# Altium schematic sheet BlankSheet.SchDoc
size 431 x 279 mm; Date: Not shown in title block; ApprovedBy: Not shown in title block; CheckedBy: Not shown in title block; Author: Not shown in title block; CompanyName: Not shown in title block; Engineer: Not shown in title block; Organization: Not shown in title block; Address1: Not shown in title block; Address2: Not shown in title block; Address3: Not shown in title block; Address4: Not shown in title block; DocumentNumber: 1; Revision: Use project parameter SCH_Rev; SheetNumber: 2; SheetTotal: 3; PageSetup: Record=PageOptions¦CenterHorizontal=True¦CenterVertical=True¦PrintScale=1.00¦XCorrection=1.00¦YCorrection=1.00¦PrintKind=0¦BorderSize=5000000¦LeftOffset=0¦BottomOffset=0¦Orientation=2¦PaperLength=1000¦PaperWidth=1000¦Scale=100¦PaperSource=15¦PrintQuality=600¦MediaType=1¦DitherType=10¦PaperKind=Letter¦PrintScaleMode=1
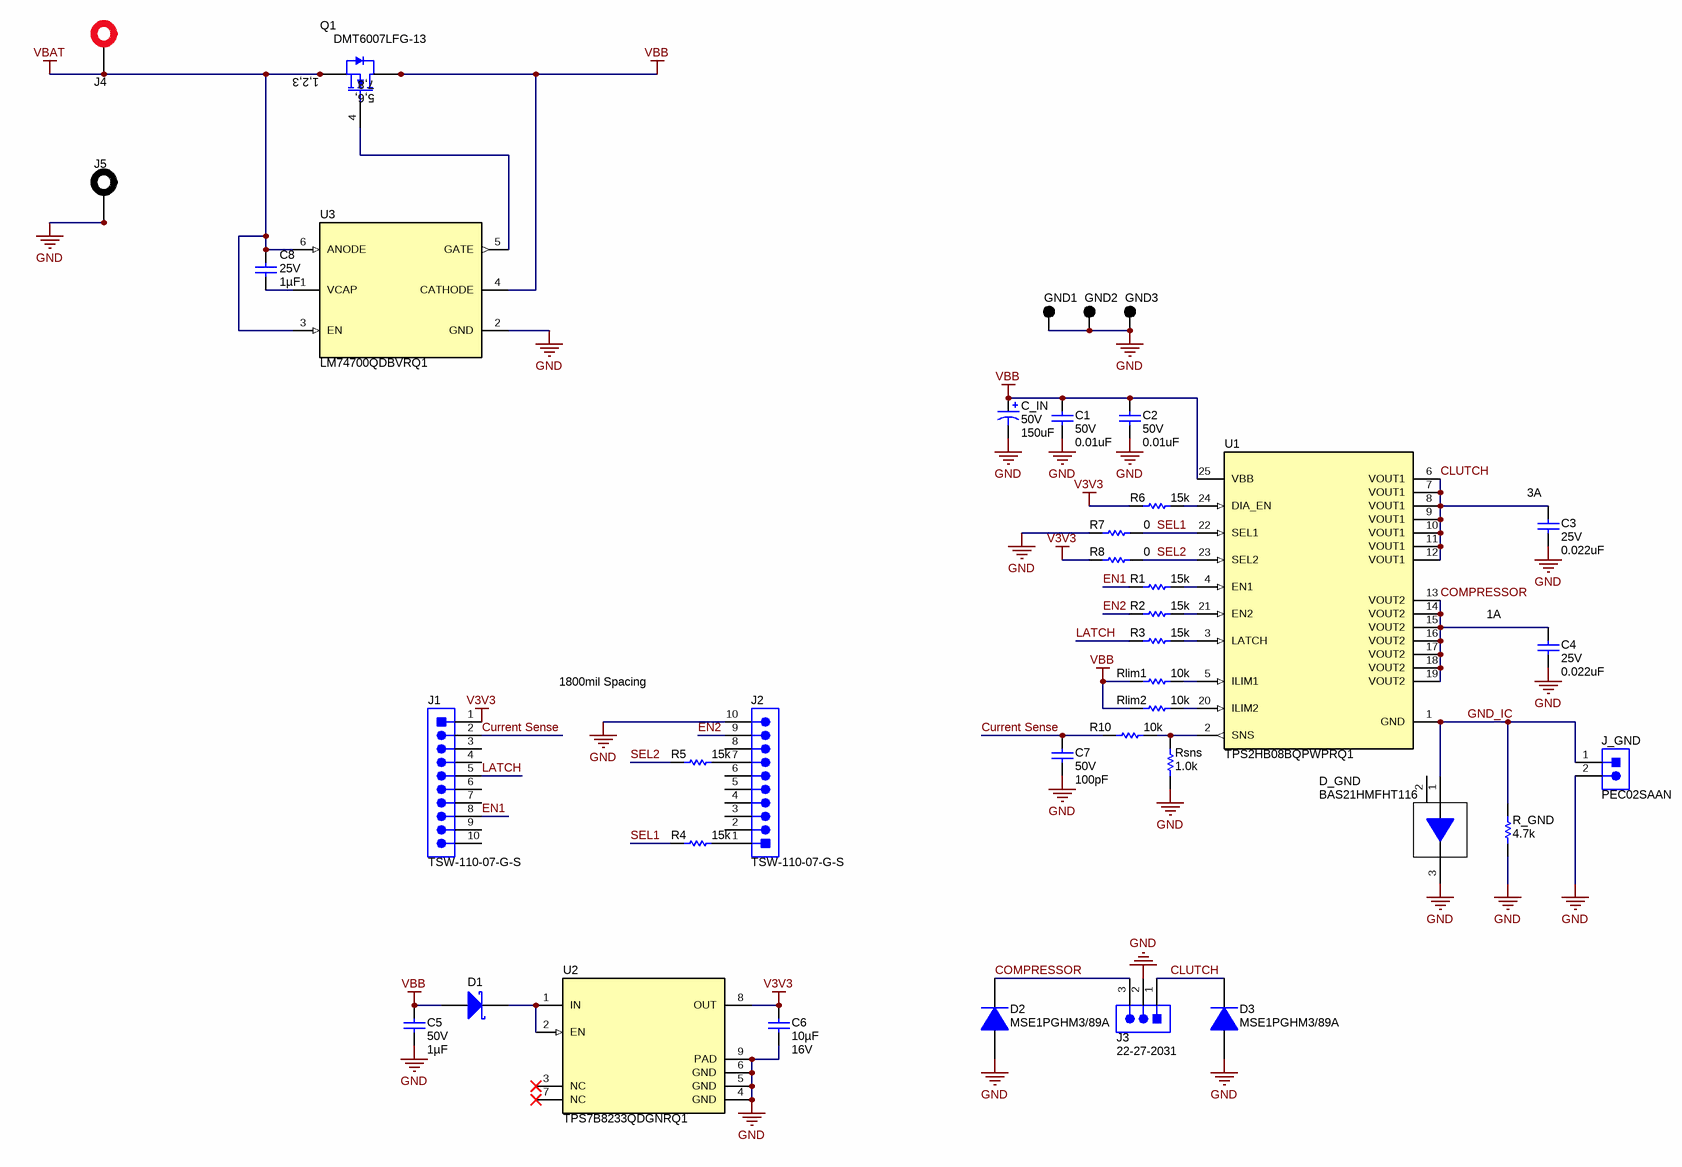
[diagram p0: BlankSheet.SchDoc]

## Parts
C1  VDC_V: 50V  ValueDisplayed: 0.01uF  [0603]  (hidden comment: GCM188R71H103KA37D)
C2  VDC_V: 50V  ValueDisplayed: 0.01uF  [0603]  (hidden comment: GCM188R71H103KA37D)
C3  VDC_V: 25V  ValueDisplayed: 0.022uF  [0603]  (hidden comment: C0603C223K3RACTU)
C4  VDC_V: 25V  ValueDisplayed: 0.022uF  [0603]  (hidden comment: C0603C223K3RACTU)
C5  VDC_V: 50V  ValueDisplayed: 1µF  [0805_HV]  (hidden comment: 08055C105K4Z2A)
C6  ValueDisplayed: 10µF  VDC_V: 16V  [0603]  (hidden comment: GRT188C81C106ME13D)
C7  VDC_V: 50V  ValueDisplayed: 100pF  [0402]  (hidden comment: CGA2B2C0G1H101J050BA)
C8  VDC_V: 25V  ValueDisplayed: 1µF  [0603]  (hidden comment: CGA3E1X7R1E105K080AD)
C_IN  VDC_V: 50V  ValueDisplayed: 150uF  [SM_RADIAL_G]  (hidden comment: EEE-FK1H151P)
D1  ZLLS400QTA  [SOD-323]  (value not drawn)
D2  MSE1PGHM3/89A  [MicroSMP]
D3  MSE1PGHM3/89A  [MicroSMP]
D_GND  BAS21HMFHT116  [SOT-23]
GND1  5011  [Keystone5011]  (value not drawn)
GND2  5011  [Keystone5011]  (value not drawn)
GND3  5011  [Keystone5011]  (value not drawn)
J1  TSW-110-07-G-S  [TSW-110-07-G-S]
J2  TSW-110-07-G-S  [TSW-110-07-G-S]
J3  22-27-2031  [MOLEX_22-27-2031]
J4  571-0500  [571-0500]  (value not drawn)
J5  571-0100  [571-0100]  (value not drawn)
J_GND  PEC02SAAN  [CONN_PEC02SAAN]
Q1  DMT6007LFG-13  [PowerDI3333-8]
R1  ValueDisplayed: 15k  [0402]  (hidden comment: CRCW040215K0JNED)
R2  ValueDisplayed: 15k  [0402]  (hidden comment: CRCW040215K0JNED)
R3  ValueDisplayed: 15k  [0402]  (hidden comment: CRCW040215K0JNED)
R4  ValueDisplayed: 15k  [0402]  (hidden comment: CRCW040215K0JNED)
R5  ValueDisplayed: 15k  [0402]  (hidden comment: CRCW040215K0JNED)
R6  ValueDisplayed: 15k  [0402]  (hidden comment: CRCW040215K0JNED)
R7  ValueDisplayed: 0  [0402]  (hidden comment: ERJ-2GE0R00X)
R8  ValueDisplayed: 0  [0402]  (hidden comment: ERJ-2GE0R00X)
R10  ValueDisplayed: 10k  [0402]  (hidden comment: CRCW040210K0JNED)
R_GND  ValueDisplayed: 4.7k  [0603]  (hidden comment: RC0603JR-074K7L)
Rlim1  ValueDisplayed: 10k  [0402]  (hidden comment: CRCW040210K0JNED)
Rlim2  ValueDisplayed: 10k  [0402]  (hidden comment: CRCW040210K0JNED)
Rsns  ValueDisplayed: 1.0k  [0603]  (hidden comment: CRCW06031K00JNEA)
U1  TPS2HB08BQPWPRQ1  [PWP0024L_N]
U2  TPS7B8233QDGNRQ1  [DGN0008D_N]
U3  LM74700QDBVRQ1  [DBV0006A_N]

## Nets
GND: C1.2 C2.2 C3.2 C4.2 C5.2 C6.2 C7.2 C_IN.2(-) D2.2(A) D3.2(A) D_GND.3(C) GND1.1 GND2.1 GND3.1 J2.10 J3.2 J5.1 J5.2 J_GND.2 R7.1 R_GND.1 Rsns.1 U2.4(GND) U2.5(GND) U2.6(GND) U2.9(PAD) U3.2(GND)
V3V3: C6.1 J1.1 R6.1 R8.1 U2.8(OUT)
VBAT: C8.2 J4.1 J4.2 Q1.1(S) Q1.2(S) Q1.3(S) U3.3(EN) U3.6(ANODE)
VBB: C1.1 C2.1 C5.1 C_IN.1(+) D1.2(A) Q1.5(D) Q1.6(D) Q1.7(D) Q1.8(D) Q1.9(D) Rlim1.1 Rlim2.1 U1.25(VBB) U3.4(CATHODE)
CLUTCH: C3.1 D3.1(K) J3.1 U1.6(VOUT1) U1.7(VOUT1) U1.8(VOUT1) U1.9(VOUT1) U1.10(VOUT1) U1.11(VOUT1) U1.12(VOUT1)
COMPRESSOR: C4.1 D2.1(K) J3.3 U1.13(VOUT2) U1.14(VOUT2) U1.15(VOUT2) U1.16(VOUT2) U1.17(VOUT2) U1.18(VOUT2) U1.19(VOUT2)
Current Sense: C7.1 J1.2 R10.1
EN1: J1.8 R1.1
EN2: J2.9 R2.1
GND_IC: D_GND.1(A) J_GND.1 R_GND.2 U1.1(GND)
LATCH: J1.5 R3.1
SEL1: R4.1 R7.2 U1.22(SEL1)
SEL2: R5.1 R8.2 U1.23(SEL2)
NetC8_1: C8.1 U3.1(VCAP)
NetD1_1: D1.1(K) U2.1(IN) U2.2(EN)
NetJ2_1: J2.1 R4.2
NetJ2_7: J2.7 R5.2
NetQ1_4: Q1.4(G) U3.5(GATE)
NetR1_2: R1.2 U1.4(EN1)
NetR2_2: R2.2 U1.21(EN2)
NetR3_2: R3.2 U1.3(LATCH)
NetR6_2: R6.2 U1.24(DIA_EN)
NetR10_2: R10.2 Rsns.2 U1.2(SNS)
NetRlim1_2: Rlim1.2 U1.5(ILIM1)
NetRlim2_2: Rlim2.2 U1.20(ILIM2)

Not connected (* = marked no-connect by the designer): D_GND 2(NC); J1 3 4 6 7 9 10; J2 2 3 4 5 6 8; U2 3(NC)* 7(NC)*

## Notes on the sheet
- (near C3) 3A
- 1A
- 1800mil Spacing

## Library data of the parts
C1 C2 = CMP-0007143-4: CAP, CERM, 0.01 uF, 50 V, +/- 10%, X7R, AEC-Q200 Grade 1, 0603; Manufacturer: MuRata; TaMin_C: -55°C; Polarized: N; SizeAreaWB_mm2: 4.68; Value1: Unknown; U/M: EA; Value: 0.01uF; TaMax_C: 125°C; SizeZ_mm: 1; SizeX_mm: 1.6; SizeY_mm: 0.8; SizeArea_mm2: 1.28; AEC Qualified: Y; Cap_F: 10nF; AEC Category: Q200
C3 C4 = CMP-0006899-4: CAP, CERM, 0.022 uF, 25 V, +/- 10%, X7R, 0603; Manufacturer: Kemet; TaMin_C: -55°C; Polarized: N; SizeAreaWB_mm2: 4.68; Value1: Unknown; U/M: EA; TaMax_C: 125°C; SizeZ_mm: 1; SizeX_mm: 1.6; SizeY_mm: 0.8; SizeArea_mm2: 1.28; Cap_F: 22nF; AEC Category: Q200
C5 = CMP-0083705-1: CAP, CERM, 1 µF, 50 V,+/- 10%, X7R, AEC-Q200 Grade 1, 0805; Manufacturer: AVX; SizeAreaWB_mm2: 6.75; SizeArea_mm2: 2.5; AEC Qualified: Y; AEC Category: Q200; Value: 1uF; TaMax_C: 125°C; SizeZ_mm: 1.45; AEC Grade: 1; Polarized: N; TaMin_C: -55°C; SizeY_mm: 1.25; U/M: EA; SizeX_mm: 2; Cap_Case: 0805
C6 = CMP-0085644-1: CAP, CERM, 10 µF, 16 V,+/- 20%, X6S, AEC-Q200 Grade 2, 0603; Manufacturer: MuRata; TaMin_C: -55°C; SizeY_mm: 0.8; SizeX_mm: 1.6; SizeZ_mm: 1; SizeArea_mm2: 1.28; Value: 10uF; AEC Grade: 2; Polarized: N; U/M: EA; TaMax_C: 105°C; AEC Qualified: Y; AEC Category: Q200; SizeAreaWB_mm2: 4.68
C7 = CMP-0006308-2: CAP, CERM, 100 pF, 50 V, +/- 5%, C0G/NP0, AEC-Q200 Grade 1, 0402; Manufacturer: TDK; TaMin_C: -55°C; Polarized: N; SizeAreaWB_mm2: 3; Value1: Unknown; U/M: EA; Value: 100pF; TaMax_C: 125°C; SizeZ_mm: 0.6; SizeX_mm: 1; SizeY_mm: 0.5; AEC Qualified: Y; AEC Category: Q200
C8 = CMP-0082523-1: CAP, CERM, 1 µF, 25 V,+/- 10%, X7R, AEC-Q200 Grade 1, 0603; Manufacturer: TDK; SizeAreaWB_mm2: 4.68; SizeArea_mm2: 1.28; AEC Qualified: Y; AEC Category: Q200; Value: 1uF; TaMax_C: 125°C; SizeZ_mm: 1; Polarized: N; TaMin_C: -55°C; SizeY_mm: 0.8; U/M: EA; SizeX_mm: 1.6
C_IN = CMP-0011178-2: CAP, AL, 150 uF, 50 V, +/- 20%, 0.18 ohm, AEC-Q200 Grade 2, SMD; Manufacturer: Panasonic; TaMin_C: -55°C; ESR_ohm: 1.8d; Polarized: Y; SizeAreaWB_mm2: 172.2; U/M: EA; Value: 150uF; TaMax_C: 105°C; SizeZ_mm: 10.2; SizeX_mm: 12; SizeY_mm: 10.3; Cap_Case: G; SizeArea_mm2: 123.6; CompType: Capacitor; Cap_F: 150µF; IRMS_A: 6.7dA; AEC Grade: 2; AEC Category: Q200
D1 = CMP-0028792-2: Diode, Schottky, 40 V, 0.52 A, AEC-Q101, SOD-323; Manufacturer: Diodes Inc.; Value: 40V; SizeZ_mm: 1; Io_A: 5.2dA; SizeAreaWB_mm2: 8.695; SizeArea_mm2: 3.645; TJmax_C: 150°C; Green_REACh: Incomplete; SizeX_mm: 2.7; AEC Category: Q101; Value1: 0.52A; SizeY_mm: 1.35; AEC Qualified: Y; Green_Lifecycle: Not Set
D2 D3 = CMP-0029173-2: Diode, Standard Recovery Rectifier, 400 V, 1 A, AEC-Q101, MicroSMP; Manufacturer: Vishay-Semiconductor; Io_A: 1A; Value2: 1.1V; AEC Qualified: Y; SizeZ_mm: 0.73; Vr_V: 600V; Value: 400V; SizeArea_mm2: 3.25; RJC_CperW: 40; Green_REACh: Incomplete; SizeAreaWB_mm2: 8.05; TJmax_C: 175°C; Green_Lifecycle: Not Set; SizeY_mm: 1.3; AEC Category: Q101; SizeX_mm: 2.5
D_GND = CMP-0080708-2: Diode, Switching, 200 V, 0.2 A, AEC-Q101, SOT-23; Manufacturer: Rohm; SizeY_mm: 3; TJmax_C: 150°C; SizeAreaWB_mm2: 14; AEC Category: Q101; Value1: 0.2A; Value: 200V; SizeZ_mm: 1.1; AEC Qualified: Y; SizeX_mm: 2.5; SizeArea_mm2: 7.5; Value2: 1.25V; Io_A: 2dA
GND1-GND3 = CMP-0055148-1: Test Point, Multipurpose, Black, TH; Manufacturer: Keystone; CNHeader: FALSE; Green_Lifecycle: Active; Green_REACh: Passed; ContactFinish: Silver; CT: TRUE
J1 J2 = CMP-0075422-1: Header, 100mil, 10x1, Gold, TH; Manufacturer: Samtec; Pitch_mm: 2.54; Cert_VDE: N; Gender: Male; Cert_CSA: Y; Voltage_V: 550V; Green_REACh: Passed; Current_A: 6.3A; CT: False; Green_Lifecycle: Active; Row_Count: 1; CNHeader: True
J3 = CMP-0055191-1: CONN HEADER 3POS .100 VERT TIN; Manufacturer: Molex; CNHeader: FALSE; Green_Lifecycle: Active; Green_REACh: Passed
J4 = CMP-0055393-3: Standard Banana Jack, insulated, 10A, red; Manufacturer: DEM Manufacturing; Green_REACh: Incomplete; Green_Lifecycle: Not Set
J5 = CMP-0055389-3: Standard Banana Jack, insulated, 10A, black; Manufacturer: DEM Manufacturing; Green_REACh: Incomplete; Green_Lifecycle: Not Set
J_GND = CMP-0002337-1: Header, 100mil, 2x1, Tin, TH; Manufacturer: Sullins Connector Solutions; CNHeader: TRUE; Current_A: 3A; Green_Lifecycle: Not Set; Shrouded: N; Gender: Male; Green_REACh: Incomplete; Voltage_V: 1.8kV; Row_Count: 1; Pitch_mm: 2.54; CT: FALSE; Cert_UL: Y
Q1 = CMP-0067553-1: MOSFET, N-CH, 60 V, 15 A, AEC-Q101, 8-PowerVDFN; Alternate Manufacturer: None; Manufacturer: Diodes Inc.; Rdson45_ohm: 8.5m; QgTyp_nC: 41.3; SizeAreaWB_mm2: 18.49; Vgs_V: 20V; Value1: 0.0085 ohm; VdsMax_V: 60V; U/M: EA; Value: 60V; IdsMax_A: 15A; SizeZ_mm: 0.8; SizeX_mm: 3.3; Value2: 41.3 nC; SizeArea_mm2: 10.89; ChType: N; AEC Qualified: Y; AEC Category: Q101
R1-R6 = CMP-0026842-3: RES, 15 k, 5%, 0.063 W, AEC-Q200 Grade 0, 0402; Manufacturer: Vishay-Dale; Power_W: 63mW; TempCo: 200 ppm/C; Value_Code: 15k0; Value: 15k; EIA_Code: E24; SizeX_mm: 1; SizeY_mm: 0.5; SizeZ_mm: 0.6; Value2: 0.063W; AEC Qualified: Y; VDC_V: 50V; AEC Category: Q200; AEC Grade: 0
R7 R8 = CMP-0026992-3: RES, 0, 5%, 0.1 W, AEC-Q200 Grade 0, 0402; Manufacturer: Panasonic; Power_W: 100mW; TempCo: 600 ppm/C; Value_Code: 0000; Value: 0; EIA_Code: E24; SizeX_mm: 1; SizeY_mm: 0.5; SizeZ_mm: 0.6; Value2: 0.1W; AEC Qualified: Y; VDC_V: 50V; AEC Category: Q200; SizeAreaWB_mm2: 3
R10 Rlim1 Rlim2 = CMP-0026825-5: RES, 10 k, 5%, 0.063 W, AEC-Q200 Grade 0, 0402; Manufacturer: Vishay-Dale; Power_W: 63mW; TempCo: 200 ppm/C; Value_Code: 10k0; Value: 10k; EIA_Code: E24; SizeX_mm: 1; SizeY_mm: 0.5; SizeZ_mm: 0.6; Value2: 0.063W; AEC Qualified: Y; VDC_V: 50V; AEC Category: Q200; AEC Grade: 0
R_GND = CMP-0025927-5: RES, 4.7 k, 5%, 0.1 W, 0603; Manufacturer: Yageo; Power_W: 100mW; TempCo: 100 ppm/C; Value_Code: 4k70; Value: 4.7k; EIA_Code: E24; SizeX_mm: 1.6; SizeY_mm: 0.8; SizeZ_mm: 1; Value2: 0.1W; SizeArea_mm2: 1.28; AEC Qualified: N; VDC_V: 75V; AEC Category: Q200; SizeAreaWB_mm2: 4.68
Rsns = CMP-0025729-4: RES, 1.0 k, 5%, 0.1 W, AEC-Q200 Grade 0, 0603; Manufacturer: Vishay-Dale; Power_W: 100mW; TempCo: 200 ppm/C; Value_Code: 1k00; Value: 1.0k; EIA_Code: E24; Res_ohm: 1k; SizeX_mm: 1.6; SizeY_mm: 0.8; SizeZ_mm: 1; Value2: 0.1W; SizeArea_mm2: 1.28; AEC Qualified: Y; VDC_V: 75V; AEC Category: Q200; AEC Grade: 0
U1 = CMP-0074891-1: 40-V, 8-mOhm Dual-Channel Smart High-Side Switch, PWP0024L (TSSOP-24); Manufacturer: Texas Instruments; SizeZ_mm: 1.2; SizeX_mm: 6.4; SizeY_mm: 7.8; SizeArea_mm2: 49.92; CompType: IC; U/M: EA; SizeAreaWB_mm2: 82.32
U2 = CMP-0013312-4: 300mA High-Voltage Ultra-Low-Iq Low-Dropout (LDO) Regulator, DGN0008D (VSSOP-8); Manufacturer: Texas Instruments; SizeX_mm: 5.05; SizeY_mm: 3.1; CompType: IC; SizeZ_mm: 1.1; SizeArea_mm2: 15.655; SizeAreaWB_mm2: 35.955; AEC Category: Q200; AEC Qualified: Y
U3 = CMP-0013281-4: Low Iq Always ON Smart Diode Controller, DBV0006A (SOT-23-6); Alternate PartNumber: LM74700QDBVTQ1; Manufacturer: Texas Instruments; SizeZ_mm: 1.45; SizeX_mm: 2.8; SizeY_mm: 2.9; SizeArea_mm2: 8.12; CompType: IC; SizeAreaWB_mm2: 14.82; AEC Category: Q200; AEC Qualified: Y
